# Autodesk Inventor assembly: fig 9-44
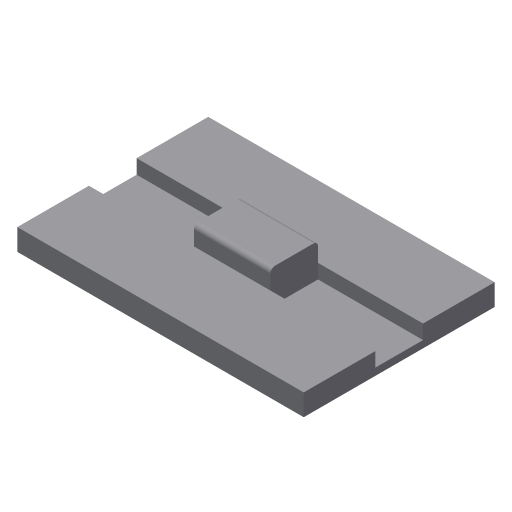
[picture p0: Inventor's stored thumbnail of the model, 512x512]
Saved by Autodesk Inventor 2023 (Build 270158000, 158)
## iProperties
Created: 2013-07
Part Number: fig 9-44
Document SubType Name: Assembly
Designer: CADCIM
Author: CADCIM
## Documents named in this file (3)
- D:\PROJECTS\Project 2022\Autodesk Inventor For Professional 2023\RESOURCES INVENTOR 2023\RESOURCES INVENTOR 2023\Inventor_2023_Part\Inventor_2023_Part\c09_Inv_2023_prt\fig 9-45.iam
- D:\PROJECTS\Project 2022\Autodesk Inventor For Professional 2023\RESOURCES INVENTOR 2023\RESOURCES INVENTOR 2023\Inventor_2023_Part\Inventor_2023_Part\c09_Inv_2023_prt\15.ipt
- D:\PROJECTS\Project 2022\Autodesk Inventor For Professional 2023\RESOURCES INVENTOR 2023\RESOURCES INVENTOR 2023\Inventor_2023_Part\Inventor_2023_Part\c09_Inv_2023_prt\16.ipt
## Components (2 placed, 2 different names)
1. 15:1 — Slider:1
2. 16:1 — Slider:1
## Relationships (1: TranslationJoint 1)
- Slider:1 [TranslationJoint]: 15:1 ↔ 16:1
